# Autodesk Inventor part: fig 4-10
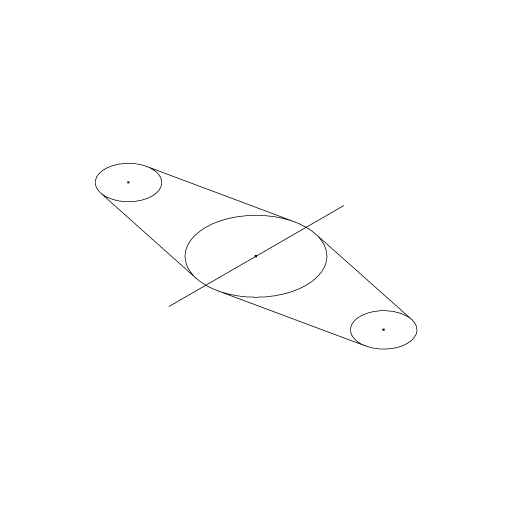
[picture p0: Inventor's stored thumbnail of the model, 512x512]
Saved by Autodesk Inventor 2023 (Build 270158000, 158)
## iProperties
Created: 2005-02
Part Number: fig 4-10
Document SubType Name: Modeling
Designer: CADCIM
Manufacturer: Standard
Standards Organization: Custom
Density: 1 g/cm^3
Material: Generic
Appearance: Default
Author: CADCIM
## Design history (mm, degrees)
sketch "Sketch1"
  geometry: L1 (-33.874, 5.844)-(-2.722, 12.469); L2 (-33.884, -5.902)-(-2.745, -12.585); L3 (-0.057, 22.288)-(-0.057, -22.318); L4 (33.759, 5.844)-(2.608, 12.469); L5 (33.77, -5.902)-(2.63, -12.585); A1 r 12.81 centre (-0.057, -0.06) between (-2.722, 12.469) and (-2.745, -12.585); A2 r 6.006 centre (-32.624, -0.03) between (-33.874, 5.844) and (-33.884, -5.902); A3 r 6.006 centre (32.51, -0.03) between (33.759, 5.844) and (33.77, -5.902)
  constraints: 10 end point, 6 point on circle, 5 symmetric about line, 4 tangent, 3 centre point, 1 vertical, 2 other
